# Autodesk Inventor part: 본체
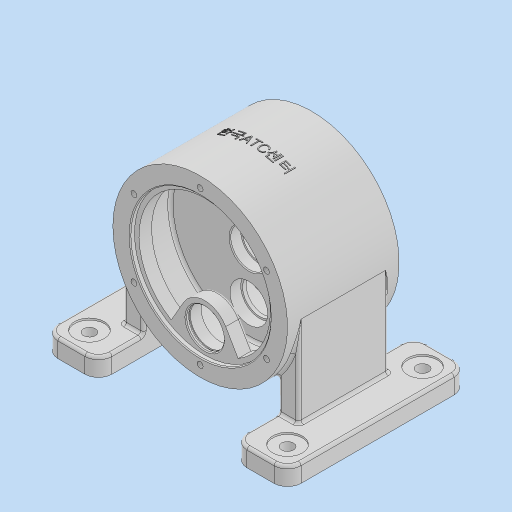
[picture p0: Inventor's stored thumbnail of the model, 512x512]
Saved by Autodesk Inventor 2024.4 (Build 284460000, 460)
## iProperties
Created: 2025-12
Part Number: 본체
Material: 일반
Document SubType Name: Modeling
Designer: home
Density: 8.94 g/cm^3
Appearance: 기본값
Mass: 18629.8 g
Surface Area: 3057.76 cm^2
Volume: 2083.88 cm^3
Author: home
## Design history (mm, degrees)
sketch "스케치1"
  geometry: L1 (-135, 100)-(135, 100); L2 (135, 100)-(135, -100); L3 (135, -100)-(-135, -100); L4 (-135, -100)-(-135, 100); L5 (-135, 100)-(135, -100); L6 (135, 100)-(-135, -100); 1 further point
  constraints: 12 end point, 2 midpoint, 2 parallel, 1 horizontal, 1 perpendicular
  dimensions: "d0" = 270 distance of L2.end L3.end; "d1" = 200 distance of L1.end L2.end
extrude "돌출1" new body sketch "스케치1" distance "d2" = 20; taper "d3" = 0 deg
sketch "스케치2"
  geometry: L1 (135, 100)-(-135, 100) reference; L2 (-75, -100)-(75, -100); L3 (75, -100)-(75, 100); L4 (75, 100)-(-75, 100); L5 (-75, 100)-(-75, -100); L6 (-75, -100)-(75, 100); L7 (75, -100)-(-75, 100); 2 further points
  constraints: 12 end point, 2 midpoint, 2 parallel, 1 horizontal, 1 perpendicular, 1 point on line
  dimensions: "d4" = 150 distance of L2.start L2.end
extrude "돌출2" cut sketch "스케치2" extent not by distance; stored distance "d5" = 0; taper "d6" = 0 deg
fillet "모깎기1" dims "d7" = 15
sketch "스케치3"
  geometry: 5 further points
  constraints: 2 horizontal alignment, 2 vertical alignment
  dimensions: "d8" = 220 distance of point (110, -75) point (-110, -75); "d9" = 110 horizontal distance of point (0, 0) point (-110, -75); "d10" = 150 distance of point (110, -75) point (110, 75); "d11" = 75 vertical distance of point (0, 0) point (110, 75)
hole "구멍1" sketch "스케치3" at (-110, -75), (110, -75), (110, 75), (-110, 75) diameter "d12" = 13.5; stored, may be unused: countersink angle "d16" = 90 deg, drill point angle "d18" = 118 deg; dims "d13" = 6, "d14" = 33, "d15" = 2, "d17" = 8
sketch "스케치4"
  geometry: C1 r 97 at (0, 120); 1 further point
  constraints: 1 centre point, 1 vertical alignment
  dimensions: "d19" = 194 diameter of C1; "d20" = 120 distance of point (0, 0) C1.centre
extrude "돌출3" join sketch "스케치4" stored distance "d21" = 124; taper "d22" = 0 deg
sketch "스케치5"
  geometry: L1 (-75, 50)-(-97, 50); L2 (-97, 50)-(-97, -50); L3 (-97, -50)-(-75, -50); L4 (-75, -50)-(-75, 50); L5 (-75, 85)-(-75, -85) reference; L6 (75, -85)-(75, 85) reference; L7 (75, 50)-(97, 50); L8 (97, 50)-(97, -50); L9 (97, -50)-(75, -50); L10 (75, -50)-(75, 50); 5 further points
  constraints: 16 end point, 4 parallel, 2 equal length, 2 horizontal, 2 horizontal alignment, 2 midpoint, 2 perpendicular, 2 vertical alignment
  dimensions: "d23" = 100 distance of L1.end L2.end; "d24" = 22 distance of L1.start L1.end
extrude "돌출4" join sketch "스케치5" stored distance "d25" = 124; taper "d26" = 0 deg
fillet "모깎기2" dims "d27" = 3
sketch "스케치6"
  geometry: L1 (-75, 58.486)-(-75, 20) reference; L2 (75, 20)-(75, 58.486) reference; L3 (-75, 20)-(-75, 0) reference; L4 (-75, 8)-(-36.6, 30.17); L5 (0, 0)-(0, 19.085); L6 (75, 8)-(36.6, 30.17); L7 (75, 0)-(75, 20) reference; L8 (90, 0)-(75, 0) reference; A1 r 97 centre (0, 120) between (-75, 58.486) and (75, 58.486) reference; 1 further point
  constraints: 6 end point, 2 symmetric about line, 1 point on circle, 1 point on line, 1 vertical
  dimensions: "d28" = 60 deg angle of L1 L4; "d97" = 8 distance from line of L6.start L8
extrude "돌출5" join sketch "스케치6" stored distance "d30" = 12; taper "d31" = 0 deg
fillet "모깎기3" dims "d32" = 3
fillet "모깎기5" dims "d34" = 3
fillet "모깎기6" dims "d35" = 3
fillet "모깎기7" dims "d36" = 3
sketch "스케치7"
  geometry: C1 r 97 at (0, 0) reference; C2 r 78 at (0, 0); 1 further point
  constraints: 1 centre point, 1 coincident
  dimensions: "d37" = 156 diameter of C2
extrude "돌출6" cut sketch "스케치7" distance "d38" = 5; taper "d39" = 0 deg
sketch "스케치8"
  geometry: L1 (-23.383, -39)-(-37.148, -62.842); L2 (23.383, -39)-(37.148, -62.842); L3 (0, -52.5)-(0, 51.479); C1 r 78 at (0, 0) reference; A1 r 73 centre (0, 0) between (-37.148, -62.842) and (37.148, -62.842); A2 r 27 centre (0, -52.5) between (-23.383, -39) and (23.383, -39); 1 further point
  constraints: 6 end point, 4 point on circle, 2 centre point, 2 tangent, 1 coincident, 1 vertical, 1 vertical alignment
  dimensions: "d40" = 146 diameter of A1; "d41" = 52.5 distance of L3.start C1.centre; "d42" = 54 diameter of A2; "d43" = 30 deg angle of L3 L1; "d44" = 30 deg angle of L3 L2
extrude "돌출7" cut sketch "스케치8" distance "d45" = 17; taper "d46" = 0 deg
chamfer "모따기1" distance "d47" = 1; stored, may be unused: second distance "d48" = 2, angle "d49" = 45 deg
sketch "스케치9"
  geometry: L1 (-23.383, -39)-(-37.148, -62.842) reference; L2 (37.148, -62.842)-(23.383, -39) reference; C1 r 87 at (0, 0); A1 r 73 centre (0, 0) between (37.148, -62.842) and (-37.148, -62.842) reference; A2 r 27 centre (0, -52.5) between (23.383, -39) and (-23.383, -39) reference; 1 further point
  constraints: 1 centre point, 1 coincident
  dimensions: "d50" = 174 diameter of C1
extrude "돌출8" cut sketch "스케치9" distance "d51" = 32; taper "d52" = 0 deg
sketch "스케치10"
  geometry: C1 r 21 at (0, -52.5); A1 r 27 centre (0, -52.5) between (23.383, -39) and (-23.383, -39) reference; 1 further point
  constraints: 1 centre point, 1 coincident
  dimensions: "d53" = 42 diameter of C1
extrude "돌출9" cut sketch "스케치10" distance "d54" = 20; taper "d55" = 0 deg
sketch "스케치11"
  geometry: L1 (-57, 46.5)-(-57, 88.5) reference; L2 (-57, 67.5)-(-26.523, 67.5); L3 (-57, 88.5)-(-40, 88.5) reference; L4 (-53.95, 88.5)-(-52, 88.5); L5 (-52, 88.5)-(-52, 89.75); L6 (-52, 89.75)-(-53.95, 89.75); L7 (-53.95, 89.75)-(-53.95, 88.5); L8 (-40, 88.5)-(-40, 46.5) reference; 2 further points
  constraints: 10 end point, 2 horizontal, 2 parallel, 1 midpoint, 1 perpendicular, 1 point on line
  dimensions: "d56" = 44.5 diameter of L6 L2; "d57" = 1.95 distance of L5.end L6.end; "d58" = 12 distance between parallel lines of L5 L8
revolve "회전1" sketch "스케치11" stored, may be unused: angle "d59" = 90 deg
sketch "스케치12"
  geometry: C1 r 21 at (0, -52.5) reference; C2 r 87 at (0, 0) reference; C3 r 21 at (0, 0); 1 further point
  constraints: 1 centre point, 1 coincident
  dimensions: "d60" = 42 diameter of C3
extrude "돌출10" cut sketch "스케치12" distance "d61" = 12; taper "d62" = 0 deg
sketch "스케치13"
  geometry: C1 r 97 at (0, 0) reference; C2 r 78 at (0, 0); 1 further point
  constraints: 1 centre point, 1 coincident
  dimensions: "d63" = 156 diameter of C2
extrude "돌출11" cut sketch "스케치13" distance "d64" = 5; taper "d65" = 0 deg
chamfer "모따기2" distance "d66" = 1; stored, may be unused: second distance "d67" = 2, angle "d68" = 45 deg
sketch "스케치14"
  geometry: C1 r 78 at (0, 0) reference; C2 r 73 at (0, 0); 1 further point
  constraints: 1 centre point, 1 coincident
  dimensions: "d69" = 146 diameter of C2
extrude "돌출12" cut sketch "스케치14" distance "d70" = 17; taper "d71" = 0 deg
sketch "스케치15"
  geometry: C1 r 73 at (0, 0) reference; C2 r 87 at (0, 0); 1 further point
  constraints: 1 centre point, 1 coincident
  dimensions: "d72" = 174 diameter of C2
extrude "돌출13" cut sketch "스케치15" distance "d73" = 32; taper "d74" = 0 deg
sketch "스케치16"
  geometry: C1 r 21 at (0, 0) reference; C2 r 21 at (0, -52.5) reference; C3 r 19 at (0, 0); C4 r 19 at (0, -52.5); 1 further point
  constraints: 2 centre point, 2 coincident
  dimensions: "d75" = 38 diameter of C3; "d76" = 38 diameter of C4
extrude "돌출14" cut sketch "스케치16" extent not by distance; stored distance "d77" = 0; taper "d78" = 0 deg
fillet "모깎기8" dims "d79" = 3
chamfer "모따기3" distance "d80" = 1; stored, may be unused: second distance "d81" = 2, angle "d82" = 45 deg
sketch "스케치17" dims "d83" = 170
  geometry: C1 r 97 at (0, 0) reference; 3 further points
  constraints: 2 vertical alignment, 1 coincident, 2 other
hole "구멍2" sketch "스케치17" at (0, 85) diameter "d84" = 6.647; stored, may be unused: countersink angle "d88" = 90 deg, drill point angle "d90" = 118 deg; dims "d85" = 16, "d86" = 33, "d87" = 2, "d89" = 18
fillet "모깎기9" dims "d94" = 3
node "작업 평면1"
sketch "스케치18"
  geometry: L1 (-59.684, 19.988)-(59.684, 19.988); L2 (59.684, 19.988)-(59.684, -19.988); L3 (59.684, -19.988)-(-59.684, -19.988); L4 (-59.684, -19.988)-(-59.684, 19.988); 4 further points
  constraints: 2 midpoint, 1 coincident, 1 horizontal alignment, 1 vertical alignment, 2 other
feature "엠보싱1" sketch "스케치18" dims "d95" = 0.5, "d96" = 0
node "솔리드1"
pattern_circular "원형 패턴1" dims angle "d92" = 360 deg
mirror "미러1"
node "투영된 루프1"
node "투영된 루프2"
node "투영된 루프3"
node "투영된 루프4"
node "투영된 루프5"
node "투영된 루프6"
feature "A9D066F2-1C7D-4E18-AEED-F7BC21143FA4" dims "d84" = 6.647, "d85" = 16, "d86" = 33, "d87" = 2, "d88" = 90 deg, "d89" = 18, "d90" = 118 deg
